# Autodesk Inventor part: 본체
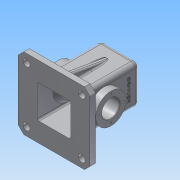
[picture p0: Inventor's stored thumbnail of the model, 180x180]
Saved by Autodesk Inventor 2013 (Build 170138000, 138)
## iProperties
Created: 2016-02
Part Number: 본체
Material: 알루미늄 6061
Document SubType Name: Modeling
Designer: Administrator
Density: 2.71 g/cm^3
Mass: 938.853 g
Surface Area: 1044.45 cm^2
Volume: 346.44 cm^3
Author: Administrator
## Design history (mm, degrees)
sketch "스케치1"
  geometry: L1 (-35, 65)-(35, 65); L2 (35, 65)-(35, -55); L3 (35, -55)-(-35, -55); L4 (-35, -55)-(-35, 65); 2 further points
  constraints: 8 end point, 2 parallel, 1 horizontal, 1 midpoint, 1 perpendicular, 1 vertical alignment
  dimensions: "d0" = 70 distance of L2.end L3.end; "d1" = 120 distance of L1.end L2.end; "d2" = 55 distance from line of L3 point (0, 0)
extrude "돌출1" new body sketch "스케치1" stored distance "d3" = 70; taper "d4" = 0 deg
feature "쉘1" dims "d5" = 5
sketch "스케치2"
  geometry: L1 (70, 0)-(70, -70) reference; L2 (0, 0)-(70, 0) reference; L3 (0, 0)-(0, -70) reference; L4 (70, -70)-(0, -70) reference; L5 (-30, 30)-(100, 30); L6 (100, 30)-(100, -100); L7 (100, -100)-(-30, -100); L8 (-30, -100)-(-30, 30); L9 (-30, 30)-(100, -100); L10 (100, 30)-(-30, -100); 1 further point
  constraints: 12 end point, 2 midpoint, 2 parallel, 1 horizontal, 1 perpendicular
  dimensions: "d6" = 130 distance of L6.end L7.end; "d7" = 130 distance of L5.end L6.end
extrude "돌출2" join sketch "스케치2" distance "d8" = 10; taper "d9" = 0 deg
chamfer "모따기1" distance "d10" = 10; stored, may be unused: second distance "d11" = 2, angle "d12" = 45 deg
fillet "모깎기1" dims "d13" = 8
fillet "모깎기2" dims "d14" = 8
fillet "모깎기3" dims "d15" = 3
fillet "모깎기4" dims "d16" = 3
node "작업 평면1"
sketch "스케치3"
  geometry: C1 r 20 at (-55, 65); 1 further point
  constraints: 1 centre point, 1 coincident
  dimensions: "d18" = 40 diameter of C1
extrude "돌출3" join sketch "스케치3" stored distance "d19" = 10; taper "d20" = 10 deg
sketch "스케치4"
  geometry: C1 r 27.5 at (27, 45); 1 further point
  constraints: 1 centre point, 1 coincident
  dimensions: "d21" = 55 diameter of C1
extrude "돌출4" join sketch "스케치4" distance "d22" = 13; taper "d23" = 0 deg
sketch "스케치5"
  geometry: C1 r 27.5 at (27, 55) reference; C2 r 27.5 at (27, 55); A1 r 27.5 centre (27, 55) between (0, 60.22) and (0, 49.78) reference; A2 r 27.5 centre (27, 55) between (54, 60.22) and (0, 60.22) reference; A3 r 27.5 centre (27, 55) between (54, 49.78) and (54, 60.22) reference; A4 r 27.5 centre (27, 55) between (0, 49.78) and (54, 49.78) reference; 1 further point
  constraints: 1 centre point, 1 coincident
  dimensions: "d24" = 55 diameter of C2
extrude "돌출5" join sketch "스케치5" distance "d25" = 7; taper "d26" = -45 deg
hole "구멍1" diameter "d29" = 32; stored, may be unused: countersink angle "d33" = 90 deg, drill point angle "d35" = 118 deg; dims "d27" = 10, "d28" = 10, "d30" = 6, "d31" = 4, "d32" = 2, "d34" = 8
hole "구멍2" diameter "d38" = 21; stored, may be unused: countersink angle "d42" = 90 deg, drill point angle "d44" = 118 deg; dims "d36" = 10, "d37" = 10, "d39" = 6, "d40" = 28, "d41" = 4, "d43" = 8
chamfer "모따기2" distance "d45" = 1; stored, may be unused: second distance "d46" = 2, angle "d47" = 45 deg
sketch "스케치6"
  geometry: L1 (-45, 35)-(57, 35) reference; L2 (-45, -55)-(-45, 55) reference; L3 (-45, 65)-(-45, 55) reference; L4 (40.069, 35)-(-45, 50); L5 (-55, 65)-(-45, 65) reference; 1 further point
  constraints: 2 end point, 2 point on line
  dimensions: "d48" = 10 deg angle of L4 L5; "d49" = 15 distance from line of L4.end L5
feature "리브1" sketch "스케치6" dims "d50" = 1, "d51" = 10, "d52" = 0, "d53" = 0, "d54" = 1, "d55" = 1
fillet "모깎기5" dims "d56" = 3
fillet "모깎기6" dims "d57" = 3
fillet "모깎기7" dims "d58" = 3
fillet "모깎기8" dims "d59" = 0.5
sketch "스케치7"
  geometry: C1 r 27.5 at (0, 0) reference; 1 further point
  constraints: 1 vertical alignment
  dimensions: "d60" = 22.5 distance of C1.centre point (0, 22.5)
hole "구멍3" sketch "스케치7" at (0, 22.5) diameter "d61" = 3.242; stored, may be unused: countersink angle "d65" = 90 deg, drill point angle "d67" = 118 deg; dims "d62" = 8, "d63" = 3, "d64" = 4, "d66" = 10
sketch "스케치8"
  geometry: L1 (7, 18)-(47, 18) reference; L2 (62, -99)-(62, 0) reference; 1 further point
  constraints: 1 other
  dimensions: "d71" = 30 distance from line of point (27, -12) L1; "d72" = 35 distance from line of point (27, -12) L2
feature "엠보싱1" sketch "스케치8" dims "d0" = 70, "d1" = 120, "d2" = 55, "d6" = 130, "d7" = 130, "d73" = 0.5, "d74" = 0
sketch "스케치9"
  geometry: L1 (0, 0)-(110, 0) reference; L2 (-10, -120)-(-10, -10) reference; C1 r 6 at (5, -15); C2 r 6 at (105, -15); 1 further point
  constraints: 2 centre point, 1 horizontal alignment
  dimensions: "d75" = 12 diameter of C1; "d76" = 15 distance from line of C1.centre L2; "d77" = 15 distance from line of C1.centre L1; "d78" = 12 diameter of C2; "d79" = 100 distance of C2.centre C1.centre
extrude "돌출6" cut sketch "스케치9" stored distance "d81" = 7; taper "d82" = 0 deg
fillet "모깎기9" dims "d83" = 3
node "솔리드1"
mirror "대칭1"
mirror "대칭2"
pattern_circular "원형 패턴1" dims angle "d69" = 360 deg
mirror "대칭3"
mirror "대칭4"
node "투영된 루프1"
